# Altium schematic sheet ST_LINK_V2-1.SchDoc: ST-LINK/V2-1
size A3; Date: Not used; ApprovedBy: Not used; CheckedBy: Not used; Author: Not used; CompanyName: STMicroelectronics; DrawnBy: Not used; Engineer: Not used; Organization: Not used; Address1: Not used; Address2: Not used; Address3: Not used; Address4: Not used; DocumentNumber: 8; Revision: Not used; SheetNumber: 8; SheetTotal: 8
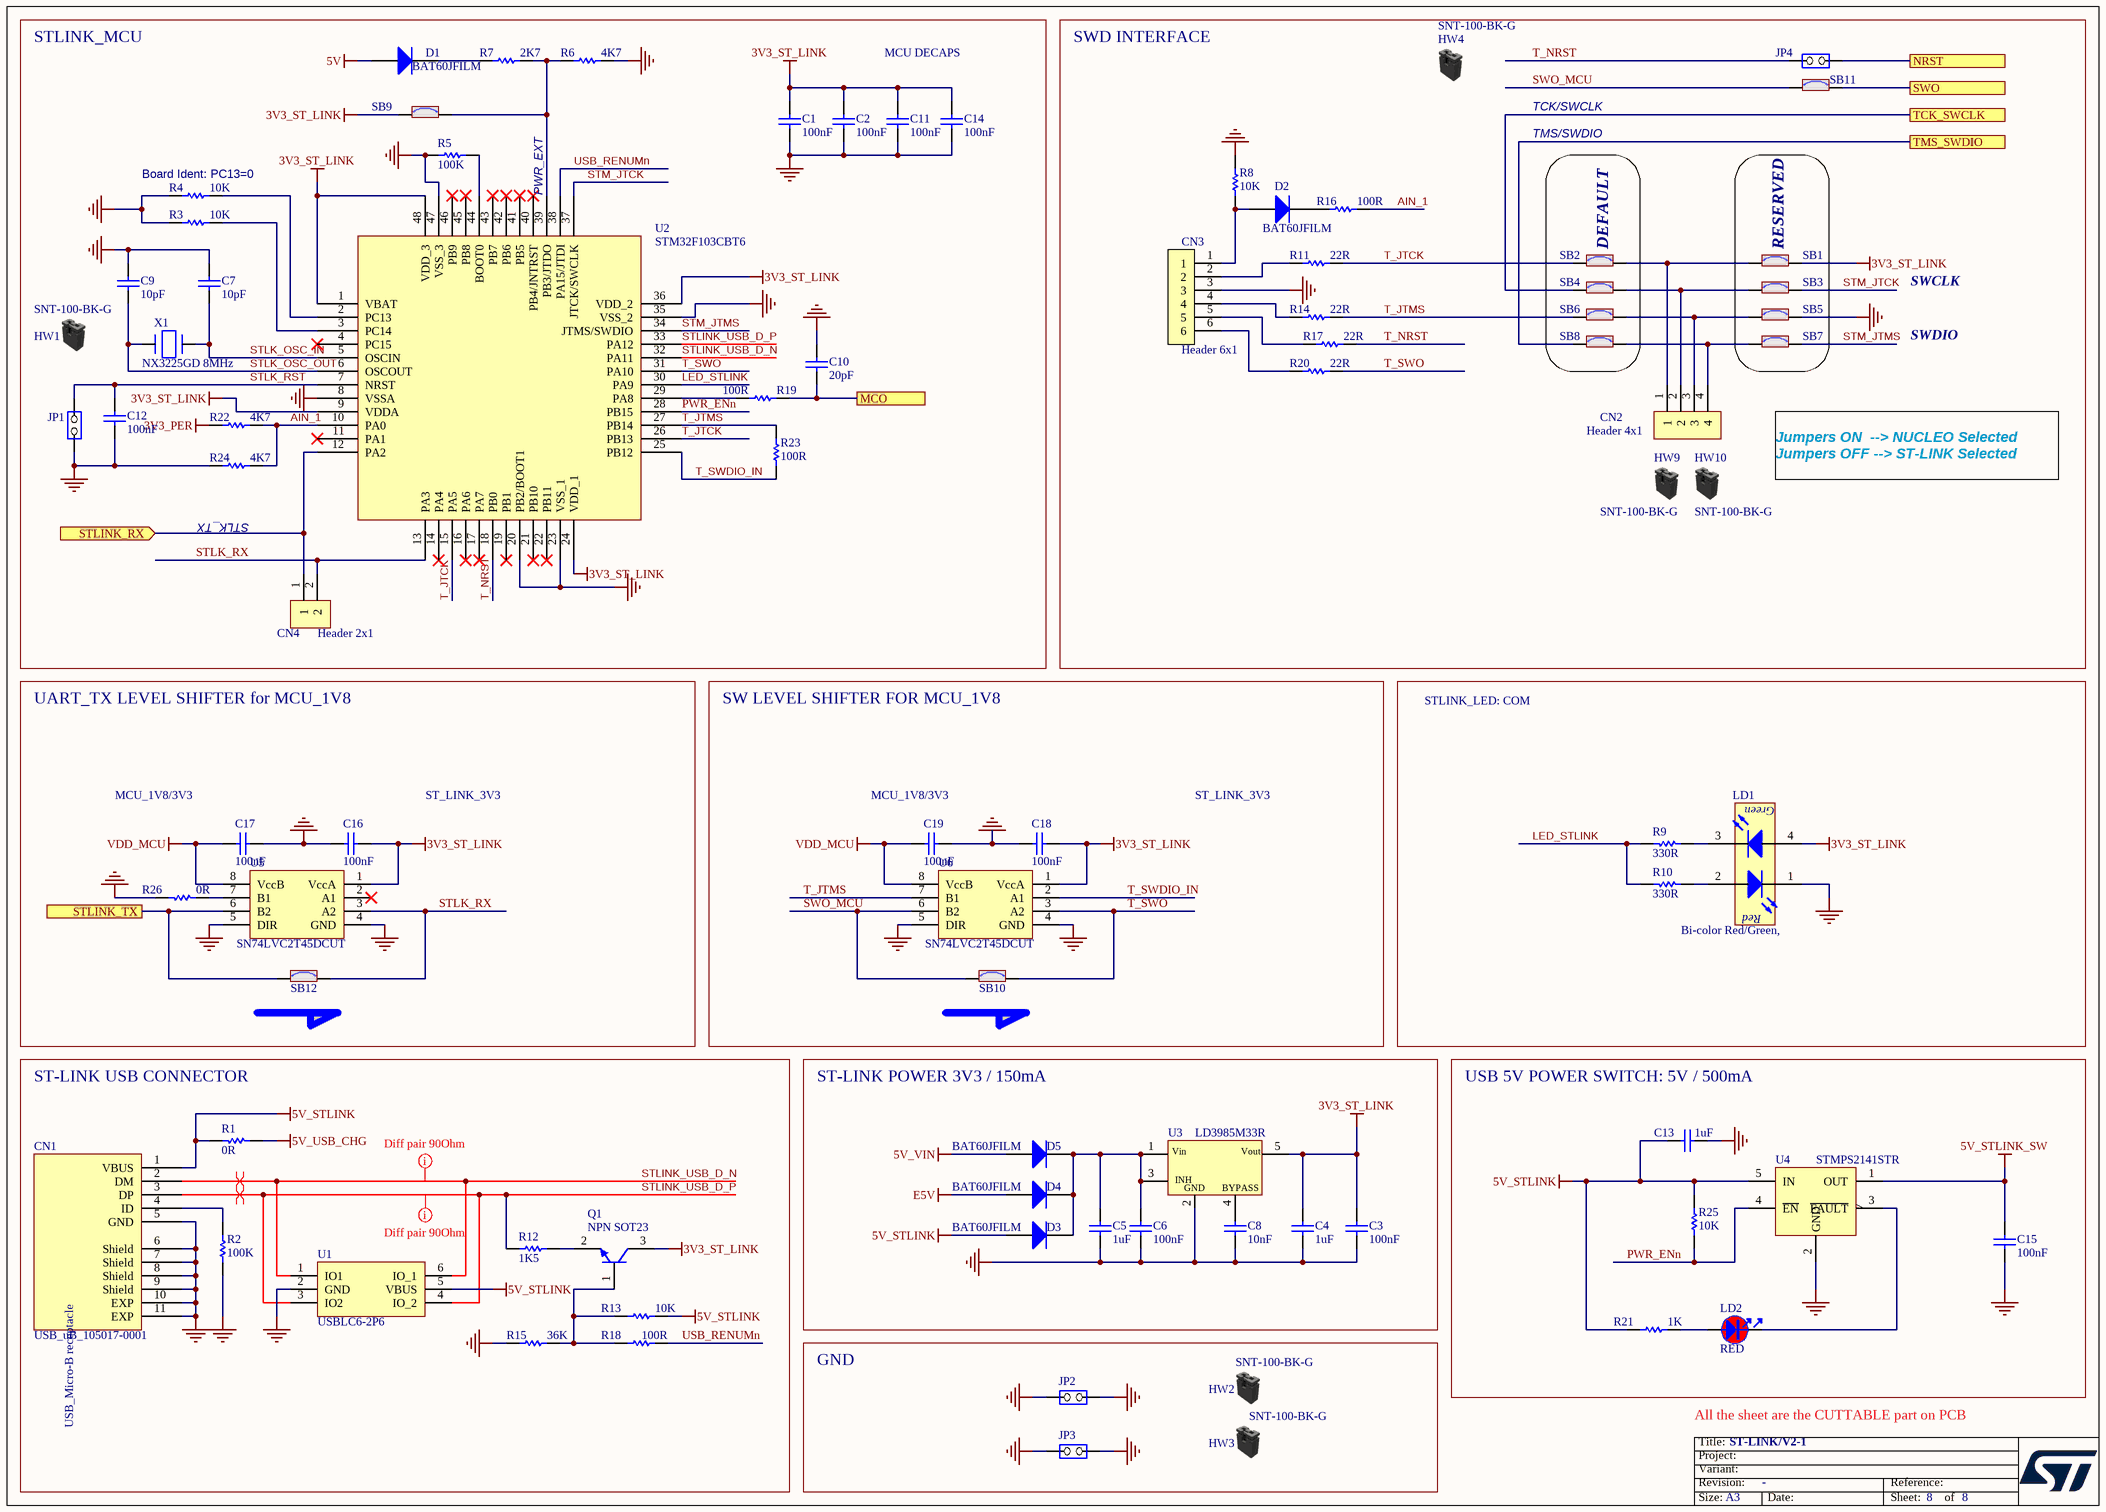
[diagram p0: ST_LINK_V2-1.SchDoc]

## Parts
C1  value 100nF  [C0603]  (hidden comment: Capacitor)
C2  value 100nF  [C0603]  (hidden comment: Capacitor)
C3  value 100nF  [C0603]  (hidden comment: Capacitor)
C4  value 1uF  [C0603]  (hidden comment: Capacitor)
C5  value 1uF  [C0603]  (hidden comment: Capacitor)
C6  value 100nF  [C0603]  (hidden comment: Capacitor)
C7  value 10pF  [C0402]  (hidden comment: Capacitor)
C8  value 10nF  [C0603]  (hidden comment: Capacitor)
C9  value 10pF  [C0402]  (hidden comment: Capacitor)
C10  value 20pF  [C0603]  (hidden comment: Capacitor)
C11  value 100nF  [C0603]  (hidden comment: Capacitor)
C12  value 100nF  [C0603]  (hidden comment: Capacitor)
C13  value 1uF  [C0603]  (hidden comment: Capacitor)
C14  value 100nF  [C0603]  (hidden comment: Capacitor)
C15  value 100nF  [C0603]  (hidden comment: Capacitor)
C16  value 100nF  [C0603]  (hidden comment: Capacitor)
C17  value 100nF  [C0603]  (hidden comment: Capacitor)
C18  value 100nF  [C0603]  (hidden comment: Capacitor)
C19  value 100nF  [C0603]  (hidden comment: Capacitor)
CN1  value USB_uB_105017-0001  [CON_USBMICROB_MOLEX_105017-0001_H2P90]  (hidden comment: USB_uB_105017.0001)
CN2  Header 4x1  [CON_SAMTEC_TSW-104-07-G-S]
CN3  Header 6x1  [CON_SAMTEC_TSW-106-07-X-S]
CN4  Header 2x1  [CON_SAMTEC_TSW-102-07-G-S]
D1  BAT60JFILM  [DIO_SOD323]
D2  BAT60JFILM  [DIO_SOD323]
D3  BAT60JFILM  [DIO_SOD323]
D4  BAT60JFILM  [DIO_SOD323]
D5  BAT60JFILM  [DIO_SOD323]
HW1  value SNT-100-BK-G  (hidden comment: Shunt Black 2.54mm)  (mechanical)
HW2  value SNT-100-BK-G  (hidden comment: Shunt Black 2.54mm)  (mechanical)
HW3  value SNT-100-BK-G  (hidden comment: Shunt Black 2.54mm)  (mechanical)
HW4  value SNT-100-BK-G  (hidden comment: Shunt Black 2.54mm)  (mechanical)
HW9  value SNT-100-BK-G  (hidden comment: Shunt Black 2.54mm)  (mechanical)
HW10  value SNT-100-BK-G  (hidden comment: Shunt Black 2.54mm)  (mechanical)
JP1  Jumper_Header 2x1  [CON_SAMTEC_TSW-102-07-G-S]  (value not drawn)
JP2  Jumper_Header 2x1  [CON_SAMTEC_TSW-102-09-X-S]  (value not drawn)
JP3  Jumper_Header 2x1  [CON_SAMTEC_TSW-102-09-X-S]  (value not drawn)
JP4  Jumper_Header 2x1  [CON_SAMTEC_TSW-102-07-G-S]  (value not drawn)
LD1  value Bi-color Red/Green,  [LED_BI-GR_HSMF-A201-A00J1]  (hidden comment: LD_BICOLOR_CMS)
LD2  value RED  [LED_0603_RED]  (hidden comment: LED_red)
Q1  value NPN SOT23  [NPN_SOT23]  (hidden comment: 9013-SOT23)
R1  value 0R  [R0603]  (hidden comment: Resistor)
R2  value 100K  [R0603]  (hidden comment: Resistor)
R3  value 10K  [R0603]  (hidden comment: Resistor)
R4  value 10K  [R0603]  (hidden comment: Resistor)
R5  value 100K  [R0603]  (hidden comment: Resistor)
R6  value 4K7  [R0603]  (hidden comment: Resistor)
R7  value 2K7  [R0603]  (hidden comment: Resistor)
R8  value 10K  [R0603]  (hidden comment: Resistor)
R9  value 330R  [R0603]  (hidden comment: Resistor)
R10  value 330R  [R0603]  (hidden comment: Resistor)
R11  value 22R  [R0603]  (hidden comment: Resistor)
R12  value 1K5  [R0603]  (hidden comment: Resistor)
R13  value 10K  [R0603]  (hidden comment: Resistor)
R14  value 22R  [R0603]  (hidden comment: Resistor)
R15  value 36K  [R0603]  (hidden comment: Resistor)
R16  value 100R  [R0603]  (hidden comment: Resistor)
R17  value 22R  [R0603]  (hidden comment: Resistor)
R18  value 100R  [R0603]  (hidden comment: Resistor)
R19  value 100R  [R0603]  (hidden comment: Resistor)
R20  value 22R  [R0603]  (hidden comment: Resistor)
R21  value 1K  [R0603]  (hidden comment: Resistor)
R22  value 4K7  [R0603]  (hidden comment: Resistor)
R23  value 100R  [R0603]  (hidden comment: Resistor)
R24  value 4K7  [R0603]  (hidden comment: Resistor)
R25  value 10K  [R0603]  (hidden comment: Resistor)
R26  value 0R  [R0603]  (hidden comment: Resistor)
SB1  SB_ON  [SOLDER-BRIDGE_R0603-0R]  (value not drawn)
SB2  SB_ON  [SOLDER-BRIDGE_R0603-0R]  (value not drawn)
SB3  SB_ON  [SOLDER-BRIDGE_R0603-0R]  (value not drawn)
SB4  SB_ON  [SOLDER-BRIDGE_R0603-0R]  (value not drawn)
SB5  SB_ON  [SOLDER-BRIDGE_R0603-0R]  (value not drawn)
SB6  SB_ON  [SOLDER-BRIDGE_R0603-0R]  (value not drawn)
SB7  SB_ON  [SOLDER-BRIDGE_R0603-0R]  (value not drawn)
SB8  SB_ON  [SOLDER-BRIDGE_R0603-0R]  (value not drawn)
SB9  SB_ON  [SOLDER-BRIDGE_R0603-0R]  (value not drawn)
SB10  SB_ON  [SOLDER-BRIDGE_R0603-0R]  (value not drawn)
SB11  SB_ON  [SOLDER-BRIDGE_R0603-0R]  (value not drawn)
SB12  SB_ON  [SOLDER-BRIDGE_R0603-0R]  (value not drawn)
U1  USBLC6-2P6  [ESD_SOT666]
U2  STM32F103CBT6  [ICC_LQFP48_7X7_P050]
U3  LD3985M33R  [REG_SOT23-5L]
U4  STMPS2141STR  [MOS_SOT23-5L]
U5  SN74LVC2T45DCUT  [ICC_VSSOP8_DCU_R-PDSO-G8_2X2P30_P050]
U6  SN74LVC2T45DCUT  [ICC_VSSOP8_DCU_R-PDSO-G8_2X2P30_P050]
X1  value NX3225GD 8MHz  [CRY_NX3225GD_2P]  (hidden comment: XTAL_2_PINS)

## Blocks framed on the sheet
STLINK_MCU: C1 C2 C7 C9-C12 C14 CN4 D1 HW1 JP1 R3-R7 R19 R22-R24 SB9 U2 X1
SWD INTERFACE: CN2 CN3 D2 HW4 HW9 HW10 JP4 R8 R11 R14 R16 R17 R20 SB11
DEFAULT: SB2 SB4 SB6 SB8
RESERVED: SB1 SB3 SB5 SB7
UART_TX LEVEL SHIFTER for MCU_1V8: C16 C17 R26 SB12 U5
SW LEVEL SHIFTER FOR MCU_1V8: C18 C19 SB10 U6
STLINK_LED: COM: LD1 R9 R10
ST-LINK USB CONNECTOR: CN1 Q1 R1 R2 R12 R13 R15 R18 U1
ST-LINK POWER 3V3 / 150mA: C3-C6 C8 D3-D5 U3
USB 5V POWER SWITCH: 5V / 500mA: C13 C15 LD2 R21 R25 U4
GND: HW2 HW3 JP2 JP3

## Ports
MCO, NRST, STLINK_RX (in), STLINK_TX, SWO, TCK_SWCLK, TMS_SWDIO

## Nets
3V3_PER: R22.1
3V3_ST_LINK: C1.2 C2.2 C3.2 C4.2 C11.2 C14.2 C16.1 C18.1 LD1.4(YellowGreen_anode) Q1.3(C) SB1.2 SB9.1 U2.1(VBAT) U2.9(VDDA) U2.24(VDD_1) U2.36(VDD_2) U2.48(VDD_3) U3.5(Vout) U5.1(VccA) U6.1(VccA)
5V: D1.1(A)
5V_STLINK: C13.1 CN1.1(VBUS) D3.1(A) R1.1 R13.1 R21.2 R25.1 U1.5(VBUS) U4.5(IN)
5V_STLINK_SW: C15.2 U4.1(OUT)
5V_USB_CHG: R1.2
5V_VIN: D5.1(A)
E5V: D4.1(A)
GND: C1.1 C2.1 C3.1 C4.1 C5.1 C6.1 C7.2 C8.1 C9.2 C10.2 C11.1 C12.1 C13.2 C14.1 C15.1 C16.2 C17.1 C18.2 C19.1 CN1.5(GND) CN1.6(Shield) CN1.7(Shield) CN1.8(Shield) CN1.9(Shield) CN1.10(EXP) CN1.11(EXP) CN3.3 JP1.1(COMMON) JP2.1(COMMON) JP2.2(NO) JP3.1(COMMON) JP3.2(NO) LD1.1(RED_cathode) R2.1 R3.1 R4.1 R5.1 R6.2 R8.2 R15.1 R24.1 R26.2 SB5.2 U1.2(GND) U2.8(VSSA) U2.20(PB2/BOOT1) U2.23(VSS_1) U2.35(VSS_2) U2.47(VSS_3) U3.2(GND) U4.2(GND) U5.4(GND) U5.5(DIR) U6.4(GND) U6.5(DIR)
VDD_MCU: C17.2 C19.2 U5.8(VccB) U6.8(VccB)
AIN_1: R16.2 R22.2 R24.2 U2.10(PA0)
LED_STLINK: R9.2 R10.2 U2.30(PA9)
MCO: C10.1 R19.2 ; port MCO
NRST: JP4.1(COMMON) ; port NRST
PWR_ENn: R25.2 U2.28(PB15) U4.4(~{EN})
STLINK_RX: CN4.1 U2.12(PA2) ; port STLINK_RX
STLINK_TX: SB12.2 U5.6(B2) ; port STLINK_TX
STLINK_USB_D_N: CN1.2(DM) U1.1(IO1) U1.6(IO_1) U2.32(PA11)
STLINK_USB_D_P: CN1.3(DP) R12.2 U1.3(IO2) U1.4(IO_2) U2.33(PA12)
STLK_OSC_IN: C7.1 U2.5(OSCIN) X1.2(X2)
STLK_OSC_OUT: C9.1 U2.6(OSCOUT) X1.1(X1)
STLK_RST: C12.2 JP1.2(NO) U2.7(NRST)
STLK_RX: CN4.2 SB12.1 U2.13(PA3) U5.3(A2)
STM_JTCK: SB3.2 U2.37(JTCK/SWCLK)
STM_JTMS: SB7.2 U2.34(JTMS/SWDIO)
SWO: SB11.2 ; port SWO
SWO_MCU: SB10.2 SB11.1 U6.6(B2)
T_JTCK: R11.2 SB2.1 U2.15(PA5) U2.26(PB13)
T_JTMS: R14.2 R23.2 SB6.1 U2.27(PB14) U6.7(B1)
T_NRST: JP4.2(NO) R17.2 U2.18(PB0)
T_SWDIO_IN: R23.1 U2.25(PB12) U6.2(A1)
T_SWO: R20.2 SB10.1 U2.31(PA10) U6.3(A2)
TCK_SWCLK: SB4.1 ; port TCK_SWCLK
TMS_SWDIO: SB8.1 ; port TMS_SWDIO
USB_RENUMn: R18.2 U2.38(PA15/JTDI)
NetC5_2: C5.2 C6.2 D3.2(K) D4.2(K) D5.2(K) U3.1(Vin) U3.3(CE)
NetC8_2: C8.2 U3.4(BYPASS)
NetCN1_4: CN1.4(ID) R2.2
NetCN2_1: CN2.1 SB1.1 SB2.2
NetCN2_2: CN2.2 SB3.1 SB4.2
NetCN2_3: CN2.3 SB5.1 SB6.2
NetCN2_4: CN2.4 SB7.1 SB8.2
NetCN3_1: CN3.1 D2.1(A) R8.1
NetCN3_2: CN3.2 R11.1
NetCN3_4: CN3.4 R14.1
NetCN3_5: CN3.5 R17.1
NetCN3_6: CN3.6 R20.1
NetD1_2: D1.2(K) R7.1
NetD2_2: D2.2(K) R16.1
NetLD1_2: LD1.2(Red_anode) R10.1
NetLD1_3: LD1.3(YellowGreen_cathode) R9.1
NetLD2_1: LD2.1 R21.1
NetLD2_2: LD2.2 U4.3(~{FAULT})
NetQ1_1: Q1.1(B) R13.2 R15.2 R18.1
NetQ1_2: Q1.2(E) R12.1
NetR3_2: R3.2 U2.3(PC14)
NetR4_2: R4.2 U2.2(PC13)
NetR5_2: R5.2 U2.44(BOOT0)
NetR6_1: R6.1 R7.2 SB9.2 U2.39(PB3/JTDO)
NetR19_1: R19.1 U2.29(PA8)
NetR26_1: R26.1 U5.7(B1)

Not connected (* = marked no-connect by the designer): U2 4(PC15)* 11(PA1)* 14(PA4)* 16(PA6)* 17(PA7)* 19(PB1)* 21(PB10)* 22(PB11)* 40(PB4/JNTRST)* 41(PB5)* 42(PB6)* 43(PB7)* 45(PB8)* 46(PB9)*; U5 2(A1)*

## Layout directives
mark named Diff pair 90Ohm: STLINK_USB_D_N, STLINK_USB_D_P
differential pair: STLINK_USB_D_N, STLINK_USB_D_P

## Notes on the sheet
- MCU DECAPS
- TCK/SWCLK
- (near R4) Board Ident: PC13=0
- TMS/SWDIO
- (near U2) PWR_EXT
- SWCLK
- SWDIO
- STLK_TX
- Jumpers ON  --> NUCLEO Selected
  Jumpers OFF --> ST-LINK Selected
- MCU_1V8/3V3
- ST_LINK_3V3
- All the sheet are the CUTTABLE part on PCB

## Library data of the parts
C1-C3 C11 C12 C14-C19 = MCD-00237: Capacitor, MLCC, 100nF, 6V3, X5R, +/-10%, 0603, T=0.8mm; Part_Preference: Not recommended; Manufacturer: YAGEO; Manufacturer_Part_Number: CC0603KRX5R5BB104; Component_Country_Of_Origin: China; ShowFields: YES; ID: 2631
C4 C13 = MCD-00238: Capacitor, MLCC, 1uF, 6V3, X5R, +/-10%, 0603, T=0,8mm; Manufacturer_Part_Number: CC0603KRX5R5BB105; Manufacturer: YAGEO; Part_Preference: Recommended
C5 = MCD-00010: Capacitor, MLCC, 1uF, 16V, X5R, +/-10%, 0603, T=0,8mm; Manufacturer_Part_Number: CC0603KRX5R7BB105; Manufacturer: YAGEO; Part_Preference: Recommended
C6 = MCD-00211: Capacitor, MLCC, 100nF, 16V, X7R, +/-10%, 0603, T=0,8mm; Manufacturer_Part_Number: CC0603KRX7R7BB104; Manufacturer: YAGEO; Part_Preference: Recommended; Order_Code_RS: 669-8763
C7 C9 = MCD-00015: Capacitor, MLCC, 10pF, 50V, NPO, +/-5%, 0402, T=0,5mm; Manufacturer_Part_Number: CC0402JRNPO9BN100; Manufacturer: YAGEO; Part_Preference: Recommended
C8 = MCD-00017: Capacitor, MLCC, 10nF, 50V, X7R, +/-10%, 0603, T=0.8mm; Manufacturer_Part_Number: CC0603KRX7R9BB103; Manufacturer: YAGEO; Part_Preference: Recommended; Order_Code_RS: 616-9537
C10 = MCD-00638: Capacitor, MLCC, 20pF, 50V, NPO, +/-5%, 0603, T=0,8mm; Manufacturer_Part_Number: CC0603JRNPO9BN200; Manufacturer: YAGEO; Part_Preference: Recommended
CN1 = MCD-00028: USB-MICRO-B, 0.65mm, RA, SMT, Bottom Mount,; Manufacturer_Part_Number: 1050170001; Manufacturer: MOLEX; Part_Type: Connector; Part_Preference: Recommended
CN2 = MCD-00029: Header, 4x1, 2,54mm, VR, TH, Height 5.84mm/2.54mm; Part_Type: Connector; Manufacturer_Part_Number: TSW-104-07-G-S; Manufacturer: SAMTEC; Part_Preference: Recommended
CN3 = MCD-00212: Header, 6x1, 2,54mm, VR, TH, Height 5.84mm/2.54mm; Manufacturer_Part_Number: TSW-106-07-G-S; Manufacturer: SAMTEC; Part_Type: Connector; Part_Preference: Recommended
CN4 = MCD-00032: Header, 2x1, 2,54mm, VR, TH, Height 5.84mm/2.54mm; Manufacturer_Part_Number: TSW-102-07-G-S; Manufacturer: SAMTEC; Part_Type: Connector; Part_Preference: Recommended; Alternate_Manufacturer: JIUBABA; Alternate_Manufacturer_Part_Number: 313102S111116
D1-D5 = MCD-00034: Manufacturer: STMICROELECTRONICS; Part_Type: Diode; BMS_Part_Number: 9151097; Part_Preference: Recommended; Manufacturer_HQ_COO: EU
HW1-HW4 HW9 HW10 = MCD-00043: SHUNT 2.54mm BLACK; Manufacturer: SAMTEC; Part_Type: Misc; Part_Preference: Recommended; Alternate_Manufacturer: JIUBABA; Alternate_Manufacturer_Part_Number: 316102S111A
JP1 JP4 = MCD-00045: Header, 2x1, 2,54mm, VR, TH, Height 5.84mm/2.54mm; Manufacturer_Part_Number: TSW-102-07-G-S; Manufacturer: SAMTEC; Part_Type: Connector; Part_Preference: Recommended; Alternate_Manufacturer: JIUBABA; LIANYI; Alternate_Manufacturer_Part_Number: 313102S111116;313102S111116; Value: Shunt not fitted
JP2 JP3 = MCD-00214: Header, 2x1, 2,54mm, VR, TH, Height 5.84mm/10.16mm; Manufacturer_Part_Number: TSW-102-09-G-S; Manufacturer: SAMTEC; Part_Type: Connector; Part_Preference: Recommended; Value: Header 2x1 16mm
LD1 = MCD-02360: Led, Bi-color Red/Green, 2V4, 30mA, 4-PLCC; Manufacturer_Part_Number: 67-22VRVGC/TR8; Manufacturer: EVERLIGHT; Part_Type: Display; Part_Preference: Recommended
LD2 = MCD-02899: LED, Red, VF : Min=1.75V , Max=2.35V, 25mA, 0603; Part_Type: Display; Part_Preference: Recommended; Manufacturer: EVERLIGHT; Manufacturer_Part_Number: 19-213/R6C-AP1Q2B/5T; Full_Alternate_Internal_Part_Number: MCD-00049; Component_Country_Of_Origin: China; ShowFields: YES; ID: 5015
Q1 = MCD-00073: NPN Bipolar Transistor; Manufacturer_Part_Number: BSR14; Manufacturer: ON SEMICONDUCTOR; Part_Type: IC; Part_Preference: Recommended; Alternate_Manufacturer_Part_Number: MMBT2222LT1G / MMBT2222ALT1G / MMBT2222ALT3G
R1 R26 = MCD-00056: Resistor,0R,0603,5%,1/10W; Manufacturer_Part_Number: RC0603JR-070RL; Manufacturer: YAGEO; Part_Preference: Recommended
R2 R5 = MCD-00223: Resistor,100K,0603,1%,1/10W; Manufacturer_Part_Number: RC0603FR-07100KL; Manufacturer: YAGEO; Part_Preference: Recommended
R3 R4 R8 R13 R25 = MCD-00220: Resistor,10K,0603,1%,1/10W; Manufacturer_Part_Number: RC0603FR-0710KL; Manufacturer: YAGEO; Part_Preference: Recommended
R6 R22 R24 = MCD-00219: Resistor,4K7,0603,1%,1/10W; Manufacturer_Part_Number: RC0603FR-074K7L; Manufacturer: YAGEO; Part_Preference: Recommended
R7 = MCD-00218: Resistor,2K7,0603,1%,1/10W; Manufacturer_Part_Number: RC0603FR-072K7L; Manufacturer: YAGEO; BMS_Part_Number: 9129767; Part_Preference: Recommended
R9 R10 = MCD-00197: Resistor,330R,0603,1%,1/10W; Manufacturer_Part_Number: RC0603FR-07330RL; Manufacturer: YAGEO; BMS_Part_Number: 9129729; Part_Preference: Recommended
R11 R14 R17 R20 = MCD-00066: Resistor,22R,0603,1%,1/10W; Manufacturer_Part_Number: RC0603FR-0722RL; Manufacturer: YAGEO; Part_Preference: Recommended
R12 = MCD-00217: Resistor,1K5,0603,1%,1/10W; Manufacturer_Part_Number: RC0603FR-071K5L; Manufacturer: YAGEO; BMS_Part_Number: 9129766; Part_Preference: Recommended
R15 = MCD-00221: Resistor,36K,0603,1%,1/10W; Manufacturer_Part_Number: RC0603FR-0736KL; Manufacturer: YAGEO; Part_Preference: Recommended
R16 R18 R19 R23 = MCD-00224: Resistor,100R,0603,1%,1/10W; Manufacturer_Part_Number: RC0603FR-07100RL; Manufacturer: YAGEO; Part_Preference: Recommended
R21 = MCD-00070: Resistor,1K,0603,1%,1/10W; Manufacturer_Part_Number: RC0603FR-071KL; Manufacturer: YAGEO; Part_Preference: Recommended
SB1-SB12 = MCD-00071: Solder Bridge ON; Part_Type: Misc; Part_Preference: Recommended; Manufacturer: YAGEO; Manufacturer_Part_Number: RC0603JR-070RL
U1 = MCD-00169: USB OTG FS ESD protection; Manufacturer: STMICROELECTRONICS; Part_Type: IC; BMS_Part_Number: 9151057; Part_Preference: Recommended; Manufacturer_HQ_COO: EU
U2 = MCD-00085: Medium-density performance line ARM-based 32-bit MCU with 128KB Flash; Manufacturer: STMICROELECTRONICS; Part_Type: IC; BMS_Part_Number: 9175111; Part_Preference: Recommended; Manufacturer_HQ_COO: EU
U3 = MCD-00086: Ultra low drop-low noise BiCMOS voltage, regulators low ESR capacitors compatible; Manufacturer: STMICROELECTRONICS; Part_Type: IC; BMS_Part_Number: 9176161; Part_Preference: Recommended; Manufacturer_HQ_COO: EU
U4 = MCD-00083: Enhanced single channel power switches with active low enable pin; Part_Type: IC; Manufacturer: STMICROELECTRONICS; Alternate_Manufacturer_Part_Number: TPS2041C; Alternate_Manufacturer: TEXAS INSTRUMENTS; BMS_Part_Number: 9159003; Part_Preference: Recommended; Manufacturer_HQ_COO: EU
U5 U6 = MCD-00264: Dual bit dual supply bus transceiver; Part_Type: IC; Manufacturer: TEXAS INSTRUMENTS; BMS_Part_Number: 9169311; Part_Preference: Recommended
X1 = MCD-00092: Crystal 8MHz, 8pF, +-20ppm, 500ohms max,  SMD; Manufacturer_Part_Number: NX3225GD 8MHz EXS00A-CG04874; Manufacturer: NDK; Part_Type: Crystal oscillator; BMS_Part_Number: 9157029; Part_Preference: Recommended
